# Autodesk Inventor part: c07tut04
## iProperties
Shininess: 77.0
Length Units: 11269
Angle Units: 11279
Time Units: 11290
Mass Units: 11283
Length Display Precision: 3
Angle Display Precision: 2
Created: 2002-01
Part Number: c07tut04
Document SubType Name: Modeling
Designer: ***
Density: 1 g/cm^3
Density: 0.0
Volumn: 0.0
Area: 0.0
PropertySet Name: Model Information
Control State: 0
Master: False
Checked Out: False
Author: ***
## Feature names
1. Extrusion1
2. Extrusion2
3. Hole1
4. Extrusion3
5. FaceDraft4
6. Fillet3
